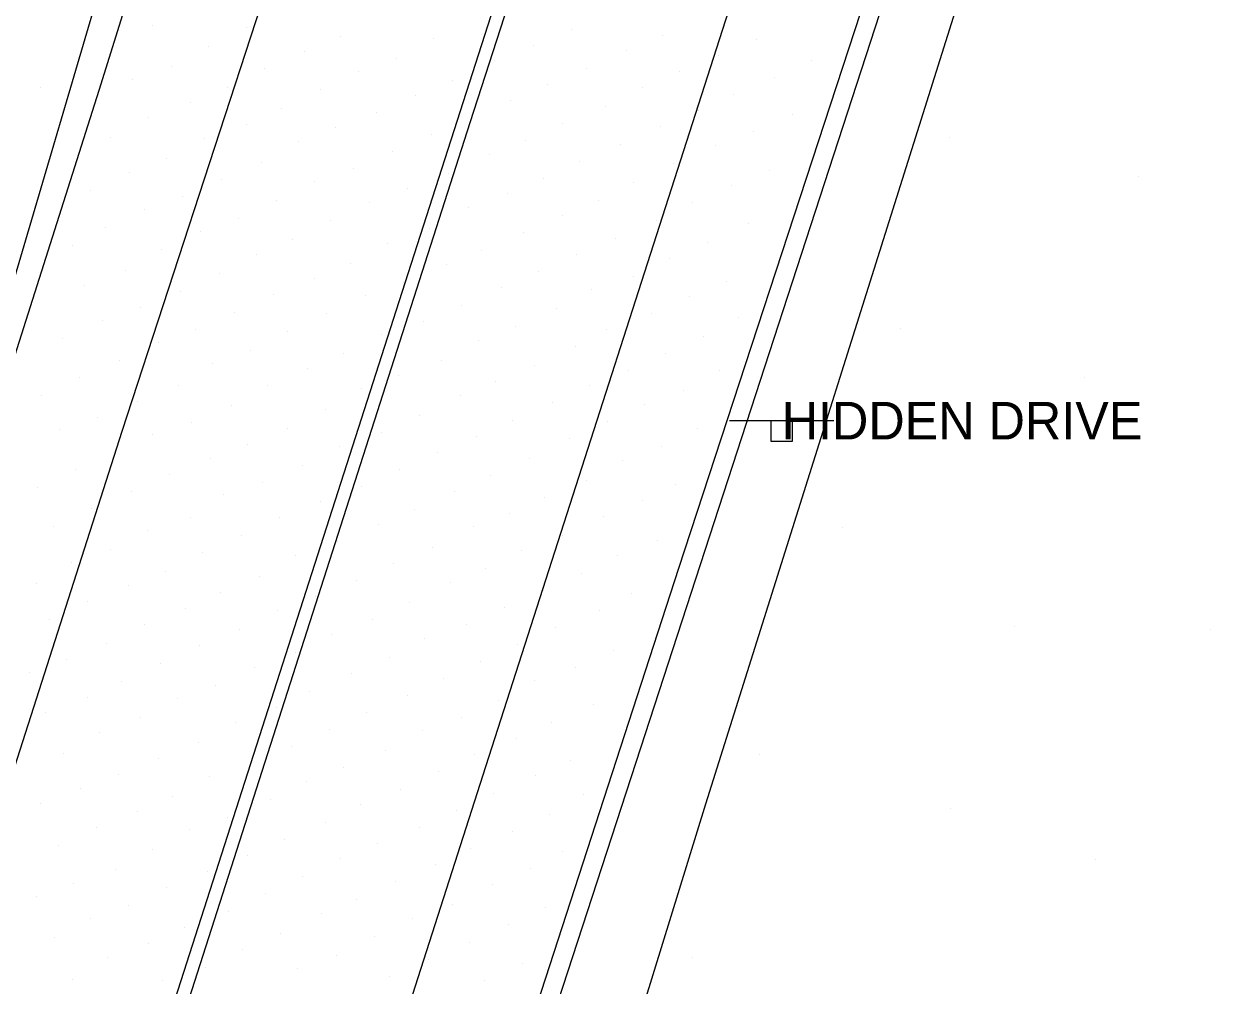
# Model space of a CAD drawing. Extents: x 0 to 1739264, y 0 to 465304.
# Drawn here: x 1738728.1 to 1738786.1, y 464325.5 to 464371.5 of the extents above; entities that cross this region are included whole.
import ezdxf

# ---------------------------------------------------------------- set-up
doc = ezdxf.new("R2010")
doc.units = 0
for name, color, linetype in [('Default', 7, 'Continuous'), ('S_Ground_SpotElevation', 7, 'Continuous'), ('S_Terrain_Flow_Arrows', 7, 'Continuous'), ('S_Terrain_Holes', 7, 'Continuous'), ('S_Terrain_Imported_Contours', 7, 'Continuous'), ('S_Terrain_Voids', 7, 'Continuous'), ('S_Text', 7, 'Continuous'), ('S_Traffic_Sign_SinglePost', 7, 'Continuous')]:
    doc.layers.add(name, color=color, linetype=linetype)

# ---------------------------------------------------------------- blocks, each defined once
blk = doc.blocks.new('POINT_DISPLAY')
at = {"layer": 'Default'}
blk.add_line((0, 0), (0, 0), dxfattribs=at)

msp = doc.modelspace()

# ---------------------------------------------------------------- linework, layer by layer
at = {"layer": 'S_Terrain_Flow_Arrows'}
for points in [[(1738688.3564, 464251.031496), (1738690.3395, 464252.589006), (1738692.1995, 464254.447298), (1738693.8343, 464256.601503), (1738695.5391, 464259.6588), (1738696.9578, 464263.416498), (1738699.9245, 464272.222398), (1738706.8015, 464293.695199), (1738713.817, 464315.630601), (1738719.9501, 464334.5338), (1738727.070999, 464357.307802), (1738732.551702, 464375.8805), (1738738.707998, 464396.955695), (1738745.1359, 464417.66822), (1738751.264203, 464435.702613), (1738755.627202, 464448.039893), (1738761.993001, 464466.083991), (1738769.246702, 464487.628089), (1738776.563199, 464508.773902), (1738783.098996, 464527.783302), (1738785.685499, 464535.356208)], [(1738814.699601, 464513.860694), (1738810.769601, 464501.415595), (1738804.535802, 464480.6529), (1738797.955503, 464459.64701), (1738789.383703, 464433.360786), (1738782.317701, 464412.184699), (1738771.242399, 464378.7378), (1738757.375898, 464336.1494), (1738748.991899, 464310.408998), (1738733.019899, 464258.787096), (1738731.302999, 464252.572801), (1738730.216299, 464247.804002), (1738729.756, 464243.515001), (1738729.589701, 464239.5011), (1738729.9867, 464238.246294), (1738730.424501, 464237.877107), (1738730.8818, 464237.704896)]]:
    msp.add_lwpolyline(points, dxfattribs=at)
at = {"layer": 'S_Terrain_Holes'}
for points in [[(1738716.6966, 464321.560701), (1738724.809099, 464346.607198), (1738731.723302, 464368.30323), (1738740.920003, 464397.747321), (1738747.284597, 464416.676521), (1738763.44, 464465.376594), (1738772.984502, 464494.583991), (1738781.924299, 464522.191291), (1738786.303217, 464535.461028), (1738793.496031, 464557.552028)], [(1738821.698218, 464537.091335), (1738814.14452, 464513.988285), (1738807.177202, 464492.764289), (1738792.837499, 464447.073188), (1738783.015798, 464417.602424), (1738771.615903, 464382.705207), (1738759.4177, 464345.420499), (1738744.8999, 464300.685602), (1738728.162701, 464246.886598)]]:
    msp.add_lwpolyline(points, dxfattribs=at)
at = {"layer": 'S_Terrain_Imported_Contours'}
for points in [[(1738798.57878, 464553.775144), (1738795.148603, 464543.193793), (1738777.288999, 464487.551887), (1738752.738599, 464413.124885), (1738732.800798, 464351.972902), (1738705.8644, 464267.857103), (1738678.827, 464185.369707), (1738654.628199, 464111.210786), (1738631.775, 464040.854188), (1738623.907904, 464015.941194)], [(1738634.454199, 464012.425111), (1738649.4289, 464058.063112), (1738670.1667, 464121.683107), (1738689.6924, 464182.041002), (1738705.9792, 464232.355607), (1738719.589001, 464274.978601), (1738734.786501, 464323.091798), (1738746.350004, 464359.089912), (1738760.277898, 464402.415473), (1738779.642698, 464461.690192), (1738793.423398, 464503.692603), (1738806.7684, 464544.685096), (1738807.560265, 464547.101191)], [(1738808.177672, 464546.642409), (1738802.293401, 464528.803291), (1738788.2553, 464485.937293), (1738775.445203, 464446.644904), (1738762.9661, 464408.493903), (1738749.4428, 464366.740302), (1738733.858499, 464318.1149), (1738717.690201, 464266.433298), (1738702.0656, 464217.993196), (1738682.1625, 464156.707994), (1738664.301699, 464101.516603), (1738635.335501, 464012.296907)], [(1738644.745199, 464009.062105), (1738654.8025, 464040.277803), (1738669.121099, 464084.176698), (1738689.2048, 464144.832002), (1738706.63, 464198.951005), (1738722.465099, 464248.7679), (1738739.417002, 464302.301599), (1738750.081598, 464335.5645), (1738762.818899, 464375.208381), (1738775.1704, 464413.370124), (1738788.2376, 464452.934486), (1738800.295598, 464489.747413), (1738816.4241, 464539.282294), (1738816.833754, 464540.526168)]]:
    msp.add_lwpolyline(points, dxfattribs=at)
at = {"layer": 'S_Terrain_Voids'}
msp.add_lwpolyline([(1738732.942598, 464244.125001), (1738760.736898, 464334.173501), (1738791.830404, 464432.979804), (1738815.289899, 464508.737312), (1738821.9792, 464528.690314), (1738826.663598, 464538.125495)], dxfattribs=at)
at = {"layer": 'S_Traffic_Sign_SinglePost'}
msp.add_line((1738761.862924, 464352.4972), (1738766.853076, 464352.4972), dxfattribs=at)
msp.add_lwpolyline([(1738763.858985, 464352.4972), (1738764.857015, 464352.4972), (1738764.857015, 464351.49917), (1738763.858985, 464351.49917)], close=True, dxfattribs=at)

# ---------------------------------------------------------------- block references
at = {"layer": 'S_Ground_SpotElevation'}
for p in [(1738734.288898, 464371.38958), (1738738.777698, 464371.311699), (1738754.316096, 464371.211662), (1738743.268596, 464370.864067), (1738747.706294, 464370.791008), (1738758.679301, 464370.939873), (1738763.149799, 464370.718986), (1738736.962299, 464370.389213), (1738741.546695, 464370.150383), (1738752.495296, 464370.416191), (1738756.933696, 464370.177055), (1738761.354396, 464369.937981), (1738735.177798, 464369.440971), (1738739.646396, 464369.34301), (1738745.917598, 464369.831962), (1738750.619495, 464369.708), (1738755.010699, 464369.34478), (1738765.789096, 464369.730095), (1738733.306399, 464368.831962), (1738744.113895, 464369.188591), (1738748.628299, 464368.769401), (1738759.493899, 464369.198479), (1738764.018695, 464368.911674), (1738728.889298, 464368.408611), (1738737.834994, 464368.42321), (1738742.285495, 464368.321586), (1738753.175395, 464368.559502), (1738757.719295, 464368.40966), (1738736.091693, 464367.702385), (1738746.849895, 464368.062309), (1738751.409198, 464367.788261), (1738762.030498, 464368.09478), (1738740.446597, 464367.435295), (1738744.962596, 464367.245964), (1738755.911098, 464367.540092), (1738760.399997, 464367.337578), (1738764.857501, 464367.145378), (1738734.074191, 464367.003105), (1738738.751102, 464366.674675), (1738743.015796, 464366.496879), (1738749.499499, 464366.925712), (1738753.8548, 464366.730095), (1738758.5834, 464366.546501), (1738732.275798, 464366.045799), (1738736.732501, 464365.979607), (1738747.605701, 464366.206962), (1738752.123401, 464365.896965), (1738763.019595, 464366.326408), (1738772.399613, 464366.049053), (1738741.228099, 464365.828483), (1738745.725696, 464365.393608), (1738756.654994, 464365.693413), (1738761.204394, 464365.644157), (1738734.941501, 464365.049614), (1738739.4798, 464364.842461), (1738750.386897, 464365.202995), (1738754.701099, 464364.872002), (1738759.1757, 464364.778679), (1738733.179698, 464364.354607), (1738743.8576, 464364.554497), (1738748.414096, 464364.30767), (1738763.775996, 464364.458794), (1738781.418198, 464364.174358), (1738737.567599, 464364.054008), (1738742.035396, 464363.925163), (1738746.467998, 464363.579216), (1738752.983501, 464364.068107), (1738757.286601, 464363.866997), (1738761.940295, 464363.758659), (1738731.310001, 464363.495293), (1738735.701602, 464363.201805), (1738740.214297, 464363.021416), (1738751.250896, 464363.345878), (1738755.581599, 464363.049309), (1738733.881602, 464362.578697), (1738744.639796, 464362.944511), (1738749.381496, 464362.692192), (1738760.078998, 464362.945671), (1738738.368999, 464362.155388), (1738742.7811, 464362.07061), (1738753.859401, 464362.288261), (1738758.357097, 464362.086174), (1738762.7476, 464361.932365), (1738732.029498, 464361.718284), (1738736.5545, 464361.529991), (1738747.528896, 464361.686211), (1738752.0013, 464361.508476), (1738730.418002, 464360.883201), (1738734.685802, 464360.694908), (1738740.970302, 464361.179314), (1738745.504794, 464360.982292), (1738750.005099, 464360.645561), (1738756.395496, 464361.199882), (1738760.803699, 464361.015983), (1738739.231898, 464360.467308), (1738754.538295, 464360.420708), (1738759.012897, 464360.273613), (1738732.993297, 464359.67971), (1738737.456599, 464359.520409), (1738743.720798, 464360.037468), (1738748.3464, 464359.951469), (1738752.715701, 464359.636284), (1738731.021197, 464358.946403), (1738742.029903, 464359.284996), (1738746.264201, 464359.127861), (1738757.277599, 464359.39611), (1738761.725696, 464359.160393), (1738735.613101, 464358.666405), (1738740.047099, 464358.550285), (1738744.457202, 464358.485313), (1738750.9658, 464358.8507), (1738755.252101, 464358.790703), (1738759.929599, 464358.41259), (1738733.6869, 464357.910301), (1738749.055797, 464357.996086), (1738753.602, 464357.8507), (1738731.865398, 464357.291099), (1738738.1953, 464357.688286), (1738742.601398, 464357.614097), (1738747.232501, 464357.250694), (1738758.116595, 464357.631157), (1738762.2728, 464357.424065), (1738736.341998, 464356.847496), (1738740.741, 464356.756706), (1738745.217097, 464356.638908), (1738751.609996, 464356.984856), (1738755.988399, 464356.873405), (1738770.051499, 464356.880901), (1738729.980998, 464356.447899), (1738734.532802, 464356.240288), (1738749.872996, 464356.333183), (1738754.491901, 464356.047783), (1738760.631, 464356.527885), (1738738.947101, 464355.846214), (1738743.394496, 464355.72451), (1738758.811999, 464355.731499), (1738732.698596, 464355.356193), (1738737.1272, 464355.245903), (1738741.674701, 464354.980308), (1738748.0825, 464355.379692), (1738752.526797, 464355.156059), (1738757.037898, 464354.919914), (1738761.380595, 464354.873405), (1738730.7783, 464354.584404), (1738746.032199, 464354.655693), (1738750.665599, 464354.370689), (1738778.825913, 464354.551678), (1738728.945903, 464353.715507), (1738735.492496, 464354.176903), (1738739.789897, 464354.175987), (1738744.241901, 464354.050499), (1738755.178401, 464354.198967), (1738759.675899, 464353.937858), (1738733.529597, 464353.418693), (1738738.052501, 464353.223808), (1738748.980197, 464353.683189), (1738753.405002, 464353.357292), (1738757.811999, 464353.256157), (1738731.620998, 464352.657188), (1738742.543399, 464353.024711), (1738747.026698, 464352.735802), (1738729.806201, 464352.059898), (1738736.134898, 464352.425102), (1738740.7261, 464352.132011), (1738751.4649, 464352.488487), (1738756.019801, 464352.469658), (1738760.3157, 464352.120415), (1738734.287799, 464351.840507), (1738738.802196, 464351.375786), (1738745.211299, 464351.909386), (1738749.7718, 464351.72921), (1738754.229999, 464351.625206), (1738732.493503, 464350.963493), (1738743.2336, 464351.243095), (1738747.893298, 464350.960991), (1738758.621394, 464351.269157), (1738737.027499, 464350.701713), (1738741.426898, 464350.347404), (1738752.275897, 464350.672111), (1738756.727199, 464350.594993), (1738730.589397, 464350.183586), (1738735.101497, 464349.931999), (1738746.061198, 464350.147392), (1738750.441997, 464349.889793), (1738755.020099, 464349.658501), (1738728.759601, 464349.300712), (1738733.245196, 464349.119102), (1738739.525096, 464349.556785), (1738744.254802, 464349.334587), (1738748.715602, 464349.106102), (1738759.298801, 464349.430504), (1738737.677302, 464348.94741), (1738742.307796, 464348.645805), (1738753.018497, 464348.845604), (1738757.699496, 464348.683098), (1738731.369296, 464348.313988), (1738746.790095, 464348.246208), (1738751.348796, 464348.045311), (1738755.844997, 464347.921593), (1738729.536098, 464347.414299), (1738736.064601, 464347.880791), (1738740.363399, 464347.867912), (1738745.093303, 464347.531608), (1738749.607799, 464347.432701), (1738767.248612, 464347.395062), (1738734.036998, 464347.231895), (1738738.510997, 464347.014702), (1738753.886401, 464347.003288), (1738758.401698, 464346.786186), (1738732.238101, 464346.334892), (1738736.678302, 464346.182609), (1738743.093898, 464346.723198), (1738747.6729, 464346.450188), (1738751.932498, 464346.310387), (1738730.388698, 464345.736687), (1738741.092197, 464346.033714), (1738745.800799, 464345.66439), (1738756.5256, 464346.044914), (1738734.891101, 464345.290794), (1738739.386699, 464345.050285), (1738750.174602, 464345.421806), (1738754.7895, 464345.188988), (1738728.722697, 464344.692894), (1738733.119403, 464344.607292), (1738744.023601, 464344.864586), (1738748.500102, 464344.735802), (1738731.173, 464343.8489), (1738737.503299, 464344.260094), (1738742.086002, 464344.083092), (1738752.945598, 464344.387291), (1738757.169803, 464344.221611), (1738735.832698, 464343.514793), (1738740.223796, 464343.398186), (1738746.541896, 464343.814506), (1738751.117099, 464343.575615), (1738755.641002, 464343.400596), (1738729.350101, 464342.972893), (1738733.874499, 464342.752403), (1738744.790698, 464342.971702), (1738749.262096, 464342.758201), (1738738.439403, 464342.498009), (1738742.825297, 464342.267204), (1738753.561801, 464342.587395), (1738775.498795, 464342.669048), (1738784.863496, 464342.504253), (1738732.074397, 464341.84069), (1738736.501002, 464341.724907), (1738747.271197, 464342.064415), (1738751.741099, 464341.790092), (1738730.137096, 464341.088493), (1738741.101703, 464341.404289), (1738745.611301, 464341.166496), (1738749.944698, 464340.968498), (1738756.3203, 464341.519493), (1738728.366397, 464340.443107), (1738734.632602, 464340.885887), (1738739.1393, 464340.712913), (1738743.791896, 464340.385795), (1738754.503802, 464340.708794), (1738732.802699, 464340.017998), (1738737.2718, 464339.842796), (1738748.2074, 464340.165489), (1738752.558299, 464340.063011), (1738731.159, 464339.235802), (1738741.793399, 464339.555107), (1738746.449298, 464339.355186), (1738735.480502, 464339.200188), (1738740.191501, 464338.801597), (1738750.800296, 464339.097496), (1738755.3381, 464338.938499), (1738729.152797, 464338.55349), (1738733.712299, 464338.279808), (1738738.2196, 464338.062492), (1738744.504398, 464338.536796), (1738749.054401, 464338.302208), (1738753.3502, 464338.081688), (1738731.730395, 464337.572807), (1738742.730296, 464337.705498), (1738747.163303, 464337.691399), (1738736.446399, 464337.122307), (1738740.9108, 464336.894493), (1738751.662997, 464337.273399), (1738730.0256, 464336.567406), (1738734.540698, 464336.334709), (1738745.425998, 464336.728203), (1738749.660297, 464336.517815), (1738763.2921, 464336.507488), (1738738.975398, 464336.205406), (1738743.382899, 464335.894005), (1738754.264201, 464336.228996), (1738732.6188, 464335.5765), (1738737.013797, 464335.458397), (1738741.651996, 464335.23159), (1738747.950198, 464335.722008), (1738752.600803, 464335.539513), (1738730.8381, 464334.918907), (1738746.133998, 464334.858696), (1738750.568103, 464334.645286), (1738754.862796, 464334.625206), (1738728.8931, 464334.165001), (1738735.228, 464334.541496), (1738739.901996, 464334.356895), (1738744.228603, 464334.146995), (1738733.557498, 464333.793815), (1738737.865703, 464333.515892), (1738748.804401, 464333.869408), (1738753.268497, 464333.668999), (1738772.444199, 464333.948895), (1738731.598003, 464333.060692), (1738736.032596, 464332.92321), (1738742.557201, 464333.25869), (1738747.0311, 464333.059898), (1738751.508098, 464332.833397), (1738740.593898, 464332.460686), (1738745.046802, 464332.2575), (1738729.787997, 464332.165794), (1738734.273898, 464331.969688), (1738738.789302, 464331.692894), (1738749.488597, 464332.045891), (1738753.8735, 464331.891899), (1738743.266803, 464331.540794), (1738747.8222, 464331.277092), (1738752.326198, 464331.097191), (1738779.354508, 464331.529583), (1738732.512302, 464331.030815), (1738736.910396, 464330.937187), (1738741.440303, 464330.685112), (1738730.483897, 464330.364006), (1738734.947902, 464330.189201), (1738745.901897, 464330.452293), (1738750.551303, 464330.319694), (1738728.703799, 464329.726707), (1738739.682399, 464329.879112), (1738744.037799, 464329.596489), (1738748.637302, 464329.3731), (1738733.139499, 464329.287102), (1738737.908099, 464329.040611), (1738742.363101, 464328.913505), (1738753.058803, 464329.211296), (1738731.320399, 464328.681694), (1738735.783099, 464328.257591), (1738746.678699, 464328.673302), (1738751.306598, 464328.389305), (1738729.577098, 464327.755394), (1738740.410701, 464327.9739), (1738744.8754, 464327.846611), (1738734.086299, 464327.504387), (1738738.567401, 464327.198509), (1738749.420299, 464327.52819), (1738732.094501, 464326.804497), (1738743.069202, 464326.932701), (1738747.4854, 464326.724205), (1738751.979098, 464326.524803), (1738760.084794, 464326.809918), (1738736.7951, 464326.346611), (1738741.200198, 464326.283714), (1738745.619701, 464325.9291), (1738730.456996, 464325.776115), (1738734.768199, 464325.702598), (1738750.1403, 464325.722008)]:
    msp.add_blockref('POINT_DISPLAY', p, dxfattribs=at)

# ---------------------------------------------------------------- texts
at = {"layer": 'S_Text'}
msp.add_text('HIDDEN DRIVE', height=1.8, dxfattribs=at).set_placement((1738764.358, 464351.5972))

doc.saveas('drawing.dxf')
